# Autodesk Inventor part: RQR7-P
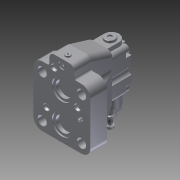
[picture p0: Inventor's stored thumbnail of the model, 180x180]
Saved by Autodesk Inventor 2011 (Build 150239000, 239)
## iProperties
Created: 2012-01
Part Number: RQR7-P
Document SubType Name: Modeling
Designer: khramov
Density: 1 g/cm^3
Author: khramov
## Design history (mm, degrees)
derived "RQR731.iam"
node "Твердое тело1"
node "0112483.ipt:1"
sketch "0550326.ipt:1"
sketch "0112484.ipt:1"
sketch "0571501.ipt:1"
sketch "0119296.ipt:1"
sketch "0530544.ipt:1"
sketch "0530329_ISO_24017___M8x40.ipt:1"
sketch "0530083_UNI_5931___M10x45.ipt:1"
sketch "0530083_UNI_5931___M10x45.ipt:2"
sketch "0530083_UNI_5931___M10x45.ipt:3"
sketch "0530083_UNI_5931___M10x45.ipt:4"
